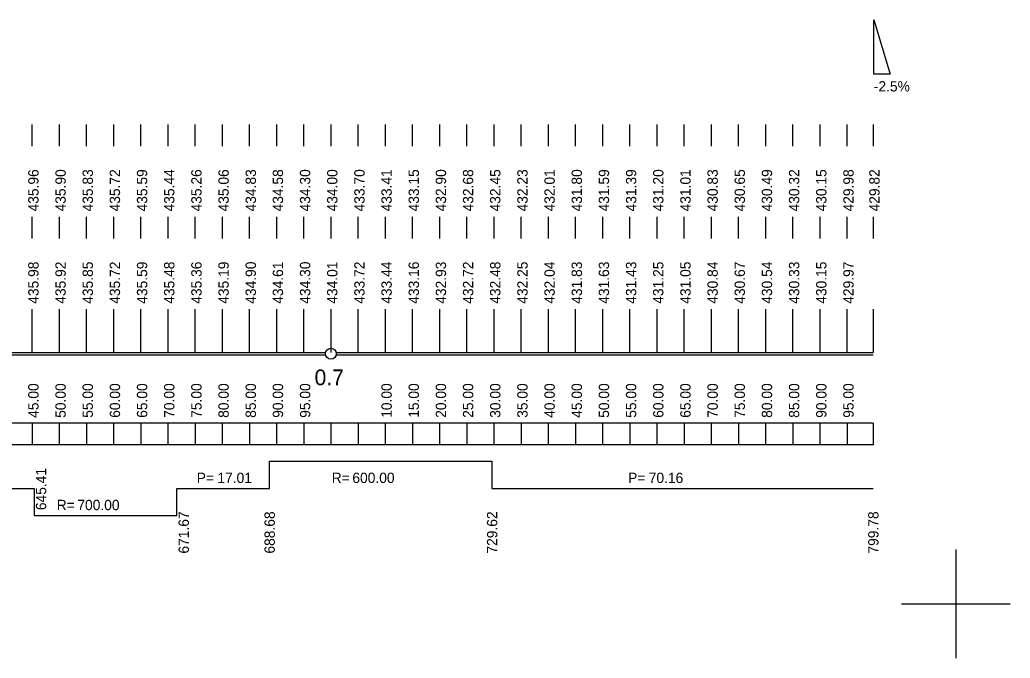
# Model space of a CAD drawing. Extents: x -240 to 1040, y 276 to 593.
# Drawn here: x 647.7 to 830, y 275.7 to 393.3 of the extents above; entities that cross this region are included whole.
import ezdxf

# ---------------------------------------------------------------- set-up
doc = ezdxf.new("R2010")
doc.units = 0
for name, color, linetype in [('1', 7, 'Continuous'), ('2', 7, 'Continuous'), ('FORMATY', 7, 'Continuous')]:
    doc.layers.add(name, color=color, linetype=linetype)

msp = doc.modelspace()

# ---------------------------------------------------------------- linework, layer by layer
at = {"layer": '1'}
for p, q in [((650, 370), (650, 374)), ((655, 374), (655, 370)), ((660, 370), (660, 374)), ((665, 374), (665, 370)), ((670, 370), (670, 374)), ((675, 374), (675, 370)), ((680, 370), (680, 374)), ((685, 374), (685, 370)), ((690, 370), (690, 374)), ((695, 374), (695, 370)), ((700, 370), (700, 374)), ((705, 374), (705, 370)), ((710, 370), (710, 374)), ((715, 374), (715, 370)), ((720, 370), (720, 374)), ((725, 374), (725, 370)), ((730, 370), (730, 374)), ((735, 374), (735, 370)), ((740, 370), (740, 374)), ((745, 374), (745, 370)), ((750, 370), (750, 374)), ((755, 374), (755, 370)), ((760, 370), (760, 374)), ((765, 374), (765, 370)), ((770, 370), (770, 374)), ((775, 374), (775, 370)), ((780, 370), (780, 374)), ((785, 374), (785, 370)), ((790, 370), (790, 374)), ((795, 374), (795, 370)), ((800, 370), (800, 374)), ((804.78, 374), (804.78, 370)), ((650, 353), (650, 357)), ((655, 357), (655, 353)), ((660, 353), (660, 357)), ((665, 357), (665, 353)), ((670, 353), (670, 357)), ((675, 357), (675, 353)), ((680, 353), (680, 357)), ((685, 357), (685, 353)), ((690, 353), (690, 357)), ((695, 357), (695, 353)), ((700, 353), (700, 357)), ((705, 357), (705, 353)), ((710, 353), (710, 357)), ((715, 357), (715, 353)), ((720, 353), (720, 357)), ((725, 357), (725, 353)), ((730, 353), (730, 357)), ((735, 357), (735, 353)), ((740, 353), (740, 357)), ((745, 357), (745, 353)), ((750, 353), (750, 357)), ((755, 357), (755, 353)), ((760, 353), (760, 357)), ((765, 357), (765, 353)), ((770, 353), (770, 357)), ((775, 357), (775, 353)), ((780, 353), (780, 357)), ((785, 357), (785, 353)), ((790, 353), (790, 357)), ((795, 357), (795, 353)), ((800, 353), (800, 357)), ((804.78, 357), (804.78, 353)), ((650, 332), (650, 340)), ((655, 340), (655, 332)), ((660, 332), (660, 340)), ((665, 340), (665, 332)), ((670, 332), (670, 340)), ((675, 340), (675, 332)), ((680, 332), (680, 340)), ((685, 340), (685, 332)), ((690, 332), (690, 340)), ((695, 340), (695, 332)), ((700, 332), (700, 340)), ((705, 340), (705, 332)), ((710, 332), (710, 340)), ((715, 340), (715, 332)), ((720, 332), (720, 340)), ((725, 340), (725, 332)), ((730, 332), (730, 340)), ((735, 340), (735, 332)), ((740, 332), (740, 340)), ((745, 340), (745, 332)), ((750, 332), (750, 340)), ((755, 340), (755, 332)), ((760, 332), (760, 340)), ((765, 340), (765, 332)), ((770, 332), (770, 340)), ((775, 340), (775, 332)), ((780, 332), (780, 340)), ((785, 340), (785, 332)), ((790, 332), (790, 340)), ((795, 340), (795, 332)), ((800, 332), (800, 340)), ((804.78, 340), (804.78, 332)), ((606, 332), (704, 332)), ((706, 332), (804.78, 332)), ((606, 331.6), (704, 331.6)), ((706, 331.6), (804.78, 331.6)), ((804.78, 319), (5, 319)), ((650, 319), (650, 315)), ((655, 319), (655, 315)), ((660, 319), (660, 315)), ((665, 319), (665, 315)), ((670, 319), (670, 315)), ((675, 319), (675, 315)), ((680, 319), (680, 315)), ((685, 319), (685, 315)), ((690, 319), (690, 315)), ((695, 319), (695, 315)), ((700, 319), (700, 315)), ((705, 319), (705, 315)), ((710, 319), (710, 315)), ((715, 319), (715, 315)), ((720, 319), (720, 315)), ((725, 319), (725, 315)), ((730, 319), (730, 315)), ((735, 319), (735, 315)), ((740, 319), (740, 315)), ((745, 319), (745, 315)), ((750, 319), (750, 315)), ((755, 319), (755, 315)), ((760, 319), (760, 315)), ((765, 319), (765, 315)), ((770, 319), (770, 315)), ((775, 319), (775, 315)), ((780, 319), (780, 315)), ((785, 319), (785, 315)), ((790, 319), (790, 315)), ((795, 319), (795, 315)), ((800, 319), (800, 315)), ((804.78, 319), (804.78, 315)), ((804.78, 315), (5, 315))]:
    msp.add_line(p, q, dxfattribs=at)
msp.add_circle((705, 331.8), 1, dxfattribs=at)
at = {"layer": '2'}
for p, q in [((804.92, 383.29), (804.92, 393.29)), ((804.92, 393.29), (807.92, 383.29)), ((804.92, 383.29), (804.92, 393.29)), ((804.92, 393.29), (807.92, 383.29)), ((804.92, 393.29), (804.92, 393.29)), ((804.92, 393.29), (804.92, 393.29)), ((804.92, 388.29), (804.92, 388.29)), ((807.92, 383.29), (804.92, 383.29)), ((807.92, 383.29), (804.92, 383.29)), ((804.92, 383.29), (804.92, 383.29)), ((804.92, 383.29), (804.92, 383.29)), ((693.68, 307), (693.68, 312)), ((693.68, 312), (734.62, 312)), ((734.62, 312), (734.62, 307)), ((525.44, 307), (650.41, 307)), ((650.41, 307), (650.41, 302)), ((676.67, 302), (676.67, 307)), ((676.67, 307), (693.68, 307)), ((734.62, 307), (804.78, 307)), ((650.41, 302), (676.67, 302))]:
    msp.add_line(p, q, dxfattribs=at)
at = {"layer": 'FORMATY'}
for p, q in [((820.02, 295.74), (820.02, 275.74)), ((820.02, 295.74), (820.02, 275.74)), ((820.02, 295.74), (820.02, 275.74)), ((820.02, 295.74), (820.02, 275.74)), ((820.02, 295.74), (820.02, 275.74)), ((820.02, 295.74), (820.02, 275.74)), ((820.02, 295.74), (820.02, 275.74)), ((820.02, 295.74), (820.02, 275.74)), ((820.02, 295.74), (820.02, 275.74)), ((810.02, 285.74), (830.02, 285.74)), ((810.02, 285.74), (830.02, 285.74)), ((810.02, 285.74), (830.02, 285.74)), ((810.02, 285.74), (830.02, 285.74)), ((810.02, 285.74), (830.02, 285.74)), ((810.02, 285.74), (830.02, 285.74)), ((810.02, 285.74), (830.02, 285.74)), ((810.02, 285.74), (830.02, 285.74)), ((810.02, 285.74), (830.02, 285.74))]:
    msp.add_line(p, q, dxfattribs=at)

# ---------------------------------------------------------------- texts
at = {"layer": '1'}
for s, p in [('435.98', (651.2, 341)), ('435.92', (656.2, 341)), ('435.85', (661.2, 341)), ('435.72', (666.2, 341)), ('435.59', (671.2, 341)), ('435.48', (676.2, 341)), ('435.36', (681.2, 341)), ('435.19', (686.2, 341)), ('434.90', (691.2, 341)), ('434.61', (696.2, 341)), ('434.30', (701.2, 341)), ('434.01', (706.2, 341)), ('433.72', (711.2, 341)), ('433.44', (716.2, 341)), ('433.16', (721.2, 341)), ('432.93', (726.2, 341)), ('432.72', (731.2, 341)), ('432.48', (736.2, 341)), ('432.25', (741.2, 341)), ('432.04', (746.2, 341)), ('431.83', (751.2, 341)), ('431.63', (756.2, 341)), ('431.43', (761.2, 341)), ('431.25', (766.2, 341)), ('431.05', (771.2, 341)), ('430.84', (776.2, 341)), ('430.67', (781.2, 341)), ('430.54', (786.2, 341)), ('430.33', (791.2, 341)), ('430.15', (796.2, 341)), ('429.97', (801.2, 341)), ('45.00', (651.2, 320)), ('50.00', (656.2, 320)), ('55.00', (661.2, 320)), ('60.00', (666.2, 320)), ('65.00', (671.2, 320)), ('70.00', (676.2, 320)), ('75.00', (681.2, 320)), ('80.00', (686.2, 320)), ('85.00', (691.2, 320)), ('90.00', (696.2, 320)), ('95.00', (701.2, 320)), ('10.00', (716.2, 320)), ('15.00', (721.2, 320)), ('20.00', (726.2, 320)), ('25.00', (731.2, 320)), ('30.00', (736.2, 320)), ('35.00', (741.2, 320)), ('40.00', (746.2, 320)), ('45.00', (751.2, 320)), ('50.00', (756.2, 320)), ('55.00', (761.2, 320)), ('60.00', (766.2, 320)), ('65.00', (771.2, 320)), ('70.00', (776.2, 320)), ('75.00', (781.2, 320)), ('80.00', (786.2, 320)), ('85.00', (791.2, 320)), ('90.00', (796.2, 320)), ('95.00', (801.2, 320))]:
    msp.add_text(s, height=1.9, rotation=90, dxfattribs=at).set_placement(p)
msp.add_text('0.7', height=2.9, dxfattribs=at).set_placement((702, 326))
at = {"layer": '2'}
for s, p in [('-2.5%', (804.92, 380.09)), ('-2.5%', (804.92, 380.09)), ('P=', (680.31, 308)), ('17.01', (684.11, 308)), ('R=', (705.15, 308)), ('600.00', (708.95, 308)), ('P=', (759.7, 308)), ('70.16', (763.5, 308)), ('R=', (654.54, 303)), ('700.00', (658.34, 303))]:
    msp.add_text(s, height=1.9, dxfattribs=at).set_placement(p)
for s, p in [('435.96', (651.2, 358)), ('435.90', (656.2, 358)), ('435.83', (661.2, 358)), ('435.72', (666.2, 358)), ('435.59', (671.2, 358)), ('435.44', (676.2, 358)), ('435.26', (681.2, 358)), ('435.06', (686.2, 358)), ('434.83', (691.2, 358)), ('434.58', (696.2, 358)), ('434.30', (701.2, 358)), ('434.00', (706.2, 358)), ('433.70', (711.2, 358)), ('433.41', (716.2, 358)), ('433.15', (721.2, 358)), ('432.90', (726.2, 358)), ('432.68', (731.2, 358)), ('432.45', (736.2, 358)), ('432.23', (741.2, 358)), ('432.01', (746.2, 358)), ('431.80', (751.2, 358)), ('431.59', (756.2, 358)), ('431.39', (761.2, 358)), ('431.20', (766.2, 358)), ('431.01', (771.2, 358)), ('430.83', (776.2, 358)), ('430.65', (781.2, 358)), ('430.49', (786.2, 358)), ('430.32', (791.2, 358)), ('430.15', (796.2, 358)), ('429.98', (801.2, 358)), ('429.82', (805.98, 358)), ('645.41', (652.61, 303)), ('671.67', (678.87, 295)), ('688.68', (694.68, 295)), ('729.62', (735.62, 295)), ('799.78', (805.78, 295))]:
    msp.add_text(s, height=1.9, rotation=90, dxfattribs=at).set_placement(p)

doc.saveas('drawing.dxf')
